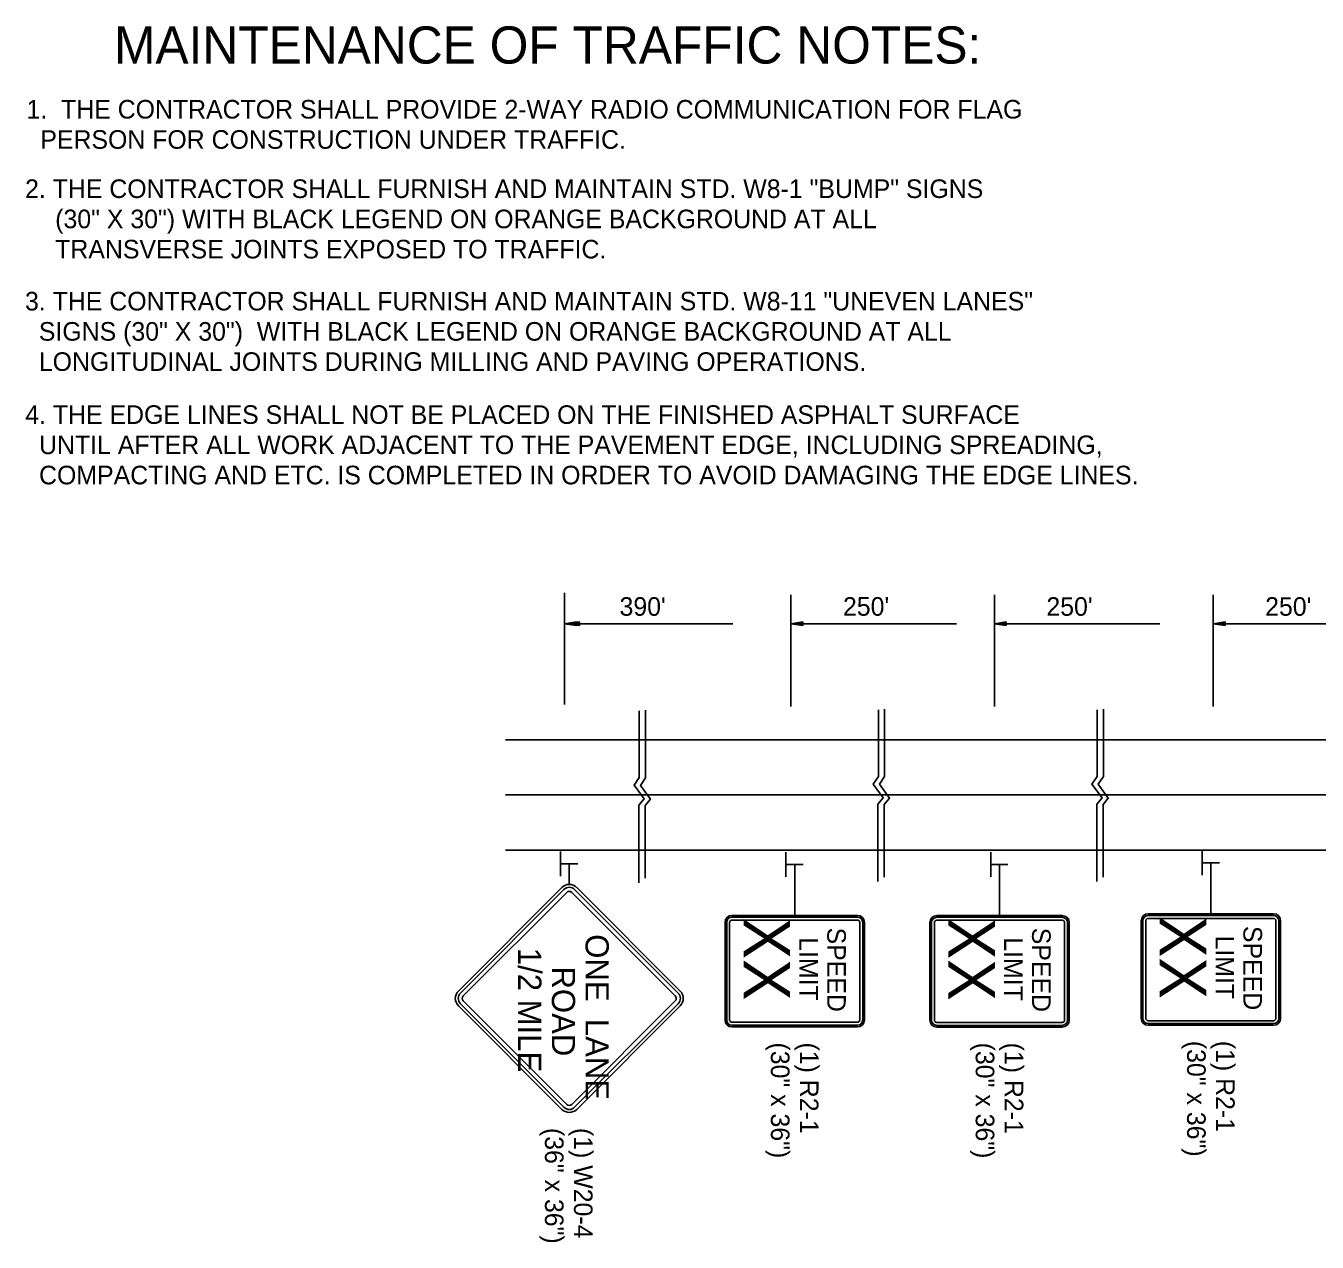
# Model space of a CAD drawing. Extents: x 1930579 to 1934718, y 596452 to 597844.
# Drawn here: x 1932288.6 to 1932705.4, y 597269.4 to 597661.8 of the extents above; entities that cross this region are included whole.
import ezdxf

# ---------------------------------------------------------------- set-up
doc = ezdxf.new("R2010")
doc.units = 0
for name, color, linetype in [('Default', 7, 'Continuous'), ('P_TC_Signs_Permanent', 7, 'Continuous'), ('P_TC_Signs_Temporary', 7, 'Continuous'), ('R_Annotation', 7, 'Continuous')]:
    doc.layers.add(name, color=color, linetype=linetype)

msp = doc.modelspace()

# ---------------------------------------------------------------- linework, layer by layer
at = {"layer": 'Default'}
for p, q in [((1932462.43, 597478.96), (1932462.43, 597442.93)), ((1932462.47, 597478.94), (1932462.47, 597442.91)), ((1932535.52, 597478.28), (1932535.52, 597442.25)), ((1932601.17, 597478.28), (1932601.17, 597442.25)), ((1932671.78, 597478.28), (1932671.78, 597442.25)), ((1932466.27, 597469.52), (1932462.43, 597468.94)), ((1932466.27, 597468.36), (1932462.43, 597468.94)), ((1932466.31, 597469.5), (1932462.47, 597468.92)), ((1932466.31, 597468.34), (1932462.47, 597468.92)), ((1932462.47, 597468.92), (1932515.87, 597468.92)), ((1932466.27, 597469.42), (1932463.07, 597468.94)), ((1932466.27, 597468.46), (1932463.07, 597468.94)), ((1932466.31, 597469.4), (1932463.11, 597468.92)), ((1932466.31, 597468.44), (1932463.11, 597468.92)), ((1932467.19, 597469.52), (1932463.36, 597468.94)), ((1932467.19, 597468.36), (1932463.36, 597468.94)), ((1932467.23, 597469.5), (1932463.39, 597468.92)), ((1932467.23, 597468.34), (1932463.39, 597468.92)), ((1932463.39, 597468.92), (1932516.8, 597468.92)), ((1932466.27, 597469.32), (1932463.73, 597468.94)), ((1932466.27, 597468.56), (1932463.73, 597468.94)), ((1932466.31, 597469.3), (1932463.77, 597468.92)), ((1932466.31, 597468.54), (1932463.77, 597468.92)), ((1932467.19, 597469.42), (1932464, 597468.94)), ((1932467.19, 597468.46), (1932464, 597468.94)), ((1932467.23, 597469.4), (1932464.04, 597468.92)), ((1932467.23, 597468.44), (1932464.04, 597468.92)), ((1932466.27, 597469.23), (1932464.37, 597468.94)), ((1932466.27, 597468.65), (1932464.37, 597468.94)), ((1932466.31, 597469.21), (1932464.41, 597468.92)), ((1932466.31, 597468.63), (1932464.41, 597468.92)), ((1932467.19, 597469.32), (1932464.66, 597468.94)), ((1932467.19, 597468.56), (1932464.66, 597468.94)), ((1932467.23, 597469.3), (1932464.7, 597468.92)), ((1932467.23, 597468.54), (1932464.7, 597468.92)), ((1932466.27, 597469.13), (1932465.02, 597468.94)), ((1932466.27, 597468.75), (1932465.02, 597468.94)), ((1932466.31, 597469.11), (1932465.06, 597468.92)), ((1932466.31, 597468.73), (1932465.06, 597468.92)), ((1932467.19, 597469.23), (1932465.3, 597468.94)), ((1932467.19, 597468.65), (1932465.3, 597468.94)), ((1932467.23, 597469.21), (1932465.33, 597468.92)), ((1932467.23, 597468.63), (1932465.33, 597468.92)), ((1932466.27, 597469.03), (1932465.66, 597468.94)), ((1932466.27, 597468.85), (1932465.66, 597468.94)), ((1932466.31, 597469.01), (1932465.7, 597468.92)), ((1932466.31, 597468.83), (1932465.7, 597468.92)), ((1932467.19, 597469.13), (1932465.95, 597468.94)), ((1932467.19, 597468.75), (1932465.95, 597468.94)), ((1932467.23, 597469.11), (1932465.99, 597468.92)), ((1932467.23, 597468.73), (1932465.99, 597468.92)), ((1932466.27, 597468.36), (1932466.27, 597469.52)), ((1932466.31, 597468.34), (1932466.31, 597469.5)), ((1932467.19, 597469.03), (1932466.59, 597468.94)), ((1932467.19, 597468.85), (1932466.59, 597468.94)), ((1932467.23, 597469.01), (1932466.63, 597468.92)), ((1932467.23, 597468.83), (1932466.63, 597468.92)), ((1932467.19, 597468.36), (1932467.19, 597469.52)), ((1932467.23, 597468.34), (1932467.23, 597469.5)), ((1932539.35, 597469.52), (1932535.52, 597468.94)), ((1932535.52, 597468.94), (1932588.92, 597468.94)), ((1932539.35, 597468.36), (1932535.52, 597468.94)), ((1932539.35, 597469.42), (1932536.16, 597468.94)), ((1932539.35, 597468.46), (1932536.16, 597468.94)), ((1932539.35, 597469.32), (1932536.82, 597468.94)), ((1932539.35, 597468.56), (1932536.82, 597468.94)), ((1932539.35, 597469.23), (1932537.46, 597468.94)), ((1932539.35, 597468.65), (1932537.46, 597468.94)), ((1932539.35, 597469.13), (1932538.11, 597468.94)), ((1932539.35, 597468.75), (1932538.11, 597468.94)), ((1932539.35, 597469.03), (1932538.75, 597468.94)), ((1932539.35, 597468.85), (1932538.75, 597468.94)), ((1932539.35, 597468.36), (1932539.35, 597469.52)), ((1932605.01, 597469.52), (1932601.17, 597468.94)), ((1932601.17, 597468.94), (1932654.57, 597468.94)), ((1932605.01, 597468.36), (1932601.17, 597468.94)), ((1932605.01, 597469.42), (1932601.81, 597468.94)), ((1932605.01, 597468.46), (1932601.81, 597468.94)), ((1932605.01, 597469.32), (1932602.47, 597468.94)), ((1932605.01, 597468.56), (1932602.47, 597468.94)), ((1932605.01, 597469.23), (1932603.11, 597468.94)), ((1932605.01, 597468.65), (1932603.11, 597468.94)), ((1932605.01, 597469.13), (1932603.76, 597468.94)), ((1932605.01, 597468.75), (1932603.76, 597468.94)), ((1932605.01, 597469.03), (1932604.4, 597468.94)), ((1932605.01, 597468.85), (1932604.4, 597468.94)), ((1932605.01, 597468.36), (1932605.01, 597469.52)), ((1932675.62, 597469.52), (1932671.78, 597468.94)), ((1932671.78, 597468.94), (1932725.18, 597468.94)), ((1932675.62, 597468.36), (1932671.78, 597468.94)), ((1932675.62, 597469.42), (1932672.42, 597468.94)), ((1932675.62, 597468.46), (1932672.42, 597468.94)), ((1932675.62, 597469.32), (1932673.08, 597468.94)), ((1932675.62, 597468.56), (1932673.08, 597468.94)), ((1932675.62, 597469.23), (1932673.72, 597468.94)), ((1932675.62, 597468.65), (1932673.72, 597468.94)), ((1932675.62, 597469.13), (1932674.37, 597468.94)), ((1932675.62, 597468.75), (1932674.37, 597468.94)), ((1932675.62, 597469.03), (1932675.01, 597468.94)), ((1932675.62, 597468.85), (1932675.01, 597468.94)), ((1932675.62, 597468.36), (1932675.62, 597469.52)), ((1932443.39, 597431.5), (1932537.33, 597431.5)), ((1932535.52, 597431.5), (1933637.52, 597431.5)), ((1932443.39, 597413.71), (1933637.52, 597413.71)), ((1932443.39, 597395.93), (1932535.52, 597395.93)), ((1932461.13, 597387.46), (1932461.13, 597395.47)), ((1932533.89, 597387.3), (1932533.89, 597395.3)), ((1932535.52, 597395.93), (1933637.52, 597395.93)), ((1932599.99, 597387.24), (1932599.99, 597395.25)), ((1932668.21, 597387.82), (1932668.21, 597395.83)), ((1932461.25, 597391.45), (1932466.71, 597391.45)), ((1932534.01, 597391.28), (1932539.47, 597391.28)), ((1932600.11, 597391.22), (1932605.57, 597391.22)), ((1932668.33, 597391.8), (1932673.79, 597391.8))]:
    msp.add_line(p, q, dxfattribs=at)
for points in [[(1932486.56, 597440.88), (1932486.56, 597419.36), (1932484.9, 597416.89), (1932488.14, 597412.46), (1932486.43, 597410.41), (1932486.43, 597385.38)], [(1932488.61, 597441.07), (1932488.61, 597419.27), (1932486.94, 597416.8), (1932490.18, 597412.37), (1932488.48, 597410.32), (1932488.47, 597386.82)], [(1932563.73, 597441.22), (1932563.73, 597419.7), (1932562.07, 597417.23), (1932565.31, 597412.8), (1932563.6, 597410.75), (1932563.6, 597385.73)], [(1932565.77, 597441.42), (1932565.77, 597419.61), (1932564.11, 597417.14), (1932567.35, 597412.71), (1932565.65, 597410.67), (1932565.64, 597387.16)], [(1932634.34, 597441.22), (1932634.34, 597419.7), (1932632.68, 597417.23), (1932635.92, 597412.8), (1932634.21, 597410.75), (1932634.21, 597385.73)], [(1932636.38, 597441.42), (1932636.38, 597419.61), (1932634.72, 597417.14), (1932637.96, 597412.71), (1932636.26, 597410.67), (1932636.25, 597387.16)]]:
    msp.add_lwpolyline(points, dxfattribs=at)
at = {"layer": 'P_TC_Signs_Permanent'}
for p, q in [((1932514.24, 597372.6), (1932514.24, 597341.1)), ((1932514.8, 597372.6), (1932514.8, 597341.1)), ((1932515.74, 597372.6), (1932515.74, 597341.1)), ((1932556.99, 597374.85), (1932516.49, 597374.85)), ((1932556.99, 597374.29), (1932516.49, 597374.29)), ((1932556.99, 597373.35), (1932516.49, 597373.35)), ((1932557.74, 597341.1), (1932557.74, 597372.6)), ((1932558.68, 597341.1), (1932558.68, 597372.6)), ((1932559.24, 597341.1), (1932559.24, 597372.6)), ((1932580.34, 597372.55), (1932580.34, 597341.05)), ((1932580.9, 597372.55), (1932580.9, 597341.05)), ((1932581.84, 597372.55), (1932581.84, 597341.05)), ((1932623.09, 597374.8), (1932582.59, 597374.8)), ((1932623.09, 597374.23), (1932582.59, 597374.23)), ((1932623.09, 597373.3), (1932582.59, 597373.3)), ((1932623.84, 597341.05), (1932623.84, 597372.55)), ((1932624.78, 597341.05), (1932624.78, 597372.55)), ((1932625.34, 597341.05), (1932625.34, 597372.55)), ((1932648.56, 597373.13), (1932648.56, 597341.63)), ((1932649.12, 597373.13), (1932649.12, 597341.63)), ((1932650.06, 597373.13), (1932650.06, 597341.63)), ((1932691.31, 597375.38), (1932650.81, 597375.38)), ((1932691.31, 597374.81), (1932650.81, 597374.81)), ((1932691.31, 597373.88), (1932650.81, 597373.88)), ((1932692.06, 597341.63), (1932692.06, 597373.13)), ((1932693, 597341.63), (1932693, 597373.13)), ((1932693.56, 597341.63), (1932693.56, 597373.13)), ((1932516.49, 597340.35), (1932556.99, 597340.35)), ((1932516.49, 597339.42), (1932556.99, 597339.42)), ((1932516.49, 597338.85), (1932556.99, 597338.85)), ((1932582.59, 597340.3), (1932623.09, 597340.3)), ((1932582.59, 597339.36), (1932623.09, 597339.36)), ((1932582.59, 597338.8), (1932623.09, 597338.8)), ((1932650.81, 597340.88), (1932691.31, 597340.88)), ((1932650.81, 597339.94), (1932691.31, 597339.94)), ((1932650.81, 597339.38), (1932691.31, 597339.38))]:
    msp.add_line(p, q, dxfattribs=at)
for centre, radius, start, end in [((1932516.49, 597372.6), 2.25, 90, 180), ((1932516.49, 597372.6), 1.69, 90, 180), ((1932516.49, 597372.6), 0.75, 90, 180), ((1932556.99, 597372.6), 2.25, 360, 90), ((1932556.99, 597372.6), 1.69, 360, 90), ((1932556.99, 597372.6), 0.75, 360, 90), ((1932582.59, 597372.55), 2.25, 90, 180), ((1932582.59, 597372.55), 1.69, 90, 180), ((1932582.59, 597372.55), 0.75, 90, 180), ((1932623.09, 597372.55), 2.25, 360, 90), ((1932623.09, 597372.55), 1.69, 360, 90), ((1932623.09, 597372.55), 0.75, 360, 90), ((1932650.81, 597373.13), 2.25, 90, 180), ((1932650.81, 597373.13), 1.69, 90, 180), ((1932650.81, 597373.13), 0.75, 90, 180), ((1932691.31, 597373.13), 2.25, 360, 90), ((1932691.31, 597373.13), 1.69, 360, 90), ((1932691.31, 597373.13), 0.75, 360, 90), ((1932516.49, 597341.1), 2.25, 180, 270), ((1932516.49, 597341.1), 1.69, 180, 270), ((1932516.49, 597341.1), 0.75, 180, 270), ((1932556.99, 597341.1), 2.25, 270, 360), ((1932556.99, 597341.1), 1.69, 270, 360), ((1932556.99, 597341.1), 0.75, 270, 360), ((1932582.59, 597341.05), 2.25, 180, 270), ((1932582.59, 597341.05), 1.69, 180, 270), ((1932582.59, 597341.05), 0.75, 180, 270), ((1932623.09, 597341.05), 2.25, 270, 360), ((1932623.09, 597341.05), 1.69, 270, 360), ((1932623.09, 597341.05), 0.75, 270, 360), ((1932650.81, 597341.63), 2.25, 180, 270), ((1932650.81, 597341.63), 1.69, 180, 270), ((1932650.81, 597341.63), 0.75, 180, 270), ((1932691.31, 597341.63), 2.25, 270, 360), ((1932691.31, 597341.63), 1.69, 270, 360), ((1932691.31, 597341.63), 0.75, 270, 360)]:
    msp.add_arc(centre, radius, start, end, dxfattribs=at)
at = {"layer": 'P_TC_Signs_Temporary'}
for p, q in [((1932428.18, 597350.45), (1932461.6, 597383.86)), ((1932428.85, 597349.79), (1932462.26, 597383.2)), ((1932429.78, 597348.86), (1932463.19, 597382.27)), ((1932464.78, 597382.27), (1932498.19, 597348.86)), ((1932465.71, 597383.2), (1932499.12, 597349.79)), ((1932466.37, 597383.86), (1932499.78, 597350.45)), ((1932463.19, 597313.86), (1932429.78, 597347.27)), ((1932498.19, 597347.27), (1932464.78, 597313.86)), ((1932461.6, 597312.27), (1932428.18, 597345.68)), ((1932462.26, 597312.93), (1932428.85, 597346.34)), ((1932499.12, 597346.34), (1932465.71, 597312.93)), ((1932499.78, 597345.68), (1932466.37, 597312.27))]:
    msp.add_line(p, q, dxfattribs=at)
for centre, radius, start, end in [((1932463.98, 597381.48), 3.37, 45, 135), ((1932463.98, 597381.48), 2.44, 45, 135), ((1932463.98, 597381.48), 1.12, 45, 135), ((1932430.57, 597348.07), 3.37, 135, 225), ((1932430.57, 597348.07), 2.44, 135, 225), ((1932430.57, 597348.07), 1.13, 135, 225), ((1932497.39, 597348.07), 1.13, 315, 45), ((1932497.39, 597348.07), 2.44, 315, 45), ((1932497.39, 597348.07), 3.37, 315, 45), ((1932463.98, 597314.66), 1.12, 225, 315), ((1932463.98, 597314.66), 3.38, 225, 315), ((1932463.98, 597314.66), 2.44, 225, 315)]:
    msp.add_arc(centre, radius, start, end, dxfattribs=at)
at = {"layer": 'R_Annotation'}
for p, q in [((1932463.98, 597391.45), (1932463.98, 597384.85)), ((1932536.74, 597391.28), (1932536.74, 597374.85)), ((1932602.84, 597391.22), (1932602.84, 597374.8)), ((1932671.06, 597391.8), (1932671.06, 597375.38))]:
    msp.add_line(p, q, dxfattribs=at)

# ---------------------------------------------------------------- texts
at = {"layer": 'Default'}
for s, p in [("390'", (1932480.2, 597471.51)), ("250'", (1932552.32, 597471.53)), ("250'", (1932617.97, 597471.51)), ("250'", (1932688.58, 597471.51))]:
    msp.add_text(s, height=6, rotation=360, dxfattribs=at).set_placement(p)
at = {"layer": 'P_TC_Signs_Permanent'}
for s, height, p in [('XX', 15, (1932520.24, 597374.15)), ('XX', 15, (1932586.34, 597374.1)), ('XX', 15, (1932654.56, 597374.68)), ('SPEED', 6, (1932547.24, 597370.92)), ('SPEED', 6, (1932613.34, 597370.87)), ('LIMIT', 6, (1932672.56, 597368.36)), ('SPEED', 6, (1932681.56, 597371.45)), ('LIMIT', 6, (1932538.24, 597367.83)), ('LIMIT', 6, (1932604.34, 597367.78))]:
    msp.add_text(s, height=height, rotation=270, dxfattribs=at).set_placement(p)
at = {"layer": 'P_TC_Signs_Temporary'}
for s, p in [('ONE  LANE', (1932469.23, 597368.77)), ('1/2 MILE', (1932447.48, 597364.38)), ('ROAD', (1932458.36, 597358.37))]:
    msp.add_text(s, height=7.5, rotation=270, dxfattribs=at).set_placement(p)
at = {"layer": 'R_Annotation'}
for s, height, rotation, p in [('MAINTENANCE OF TRAFFIC NOTES:', 12, 360, (1932317.04, 597649.67)), ('1.  THE CONTRACTOR SHALL PROVIDE 2-WAY RADIO COMMUNICATION FOR FLAG ', 6, 360, (1932288.8, 597631.93)), ('  PERSON FOR CONSTRUCTION UNDER TRAFFIC.', 6, 360, (1932288.8, 597622.18)), ('2. THE CONTRACTOR SHALL FURNISH AND MAINTAIN STD. W8-1 "BUMP" SIGNS', 6, 360, (1932288.33, 597606.3)), (' (30" X 30") WITH BLACK LEGEND ON ORANGE BACKGROUND AT ALL ', 6, 360, (1932295.83, 597596.55)), (' TRANSVERSE JOINTS EXPOSED TO TRAFFIC.', 6, 360, (1932295.83, 597586.8)), ('3. THE CONTRACTOR SHALL FURNISH AND MAINTAIN STD. W8-11 "UNEVEN LANES" ', 6, 360, (1932288.32, 597570.02)), ('  SIGNS (30" X 30")  WITH BLACK LEGEND ON ORANGE BACKGROUND AT ALL ', 6, 360, (1932288.32, 597560.27)), ('  LONGITUDINAL JOINTS DURING MILLING AND PAVING OPERATIONS.', 6, 360, (1932288.32, 597550.52)), ('4. THE EDGE LINES SHALL NOT BE PLACED ON THE FINISHED ASPHALT SURFACE', 6, 360, (1932288.39, 597533.42)), ('  UNTIL AFTER ALL WORK ADJACENT TO THE PAVEMENT EDGE, INCLUDING SPREADING,', 6, 360, (1932288.39, 597523.67)), ('  COMPACTING AND ETC. IS COMPLETED IN ORDER TO AVOID DAMAGING THE EDGE LINES.', 6, 360, (1932288.39, 597513.92)), ('(30" x 36")', 5.9996, 270, (1932529.06, 597333.85)), ('(1) R2-1', 6, 270, (1932538.42, 597333.85)), ('(30" x 36")', 5.9996, 270, (1932595.16, 597333.8)), ('(1) R2-1', 6, 270, (1932604.52, 597333.8)), ('(30" x 36")', 5.9996, 270, (1932663.38, 597334.38)), ('(1) R2-1', 6, 270, (1932672.74, 597334.38)), ('(36" x 36")', 5.9996, 270, (1932456.13, 597306.28)), ('(1) W20-4', 6, 270, (1932465.49, 597306.28))]:
    msp.add_text(s, height=height, rotation=rotation, dxfattribs=at).set_placement(p)

doc.saveas('drawing.dxf')
